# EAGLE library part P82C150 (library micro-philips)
CAN BUS I/O DEVICE, SLIO with digital and analog port functions
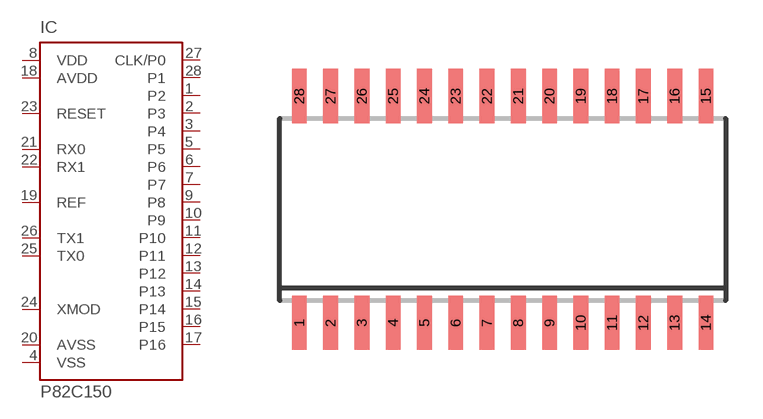
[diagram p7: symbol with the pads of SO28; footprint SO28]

Designator prefix IC

## P82C150 (OC_FARNELL: unknown; OC_NEWARK: unknown)  [SO28]
1  P2
2  P3
3  P4
4  VSS  pwr
5  P5
6  P6
7  P7
8  VDD  pwr
9  P8
10  P9
11  P10
12  P11
13  P12
14  P13
15  P14
16  P15
17  P16
18  AVDD  in
19  REF  out
20  AVSS  in
21  RX0  in
22  RX1  in
23  RESET  in
24  XMOD  in
25  TX0  out
26  TX1  out
27  CLK/P0
28  P1

## Footprint SO28 (pad centres in mm)
Small Outline Package 7.6 x 18.3 mm
smd 0.6 x 2.2: 1 -8.255,-4.6; 2 -6.985,-4.6; 3 -5.715,-4.6; 4 -4.445,-4.6; 5 -3.175,-4.6; 6 -1.905,-4.6; 7 -0.635,-4.6; 8 0.635,-4.6; 9 1.905,-4.6; 10 3.175,-4.6; 11 4.445,-4.6; 12 5.715,-4.6; 13 6.985,-4.6; 14 8.255,-4.6; 15 8.255,4.6; 16 6.985,4.6; 17 5.715,4.6; 18 4.445,4.6; 19 3.175,4.6; 20 1.905,4.6; 21 0.635,4.6; 22 -0.635,4.6; 23 -1.905,4.6; 24 -3.175,4.6; 25 -4.445,4.6; 26 -5.715,4.6; 27 -6.985,4.6; 28 -8.255,4.6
